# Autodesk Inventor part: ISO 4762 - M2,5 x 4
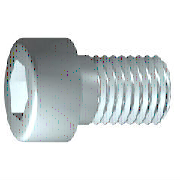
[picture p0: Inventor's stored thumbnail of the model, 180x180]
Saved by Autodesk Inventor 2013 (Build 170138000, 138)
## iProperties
Created: 2012-02
Part Number: ISO 4762 - M2,5 x 4
Material: Stainless Steel, 440C
Description: Hexagon Socket Head Cap Screw
Document SubType Name: Modeling
Standard: ISO 4762
Designer: rYan
Standard Revision: Fourth edition 2004-03-01
Standards Organization: ISO
Language: en-US
Size Designation: M2,5 x 4
Categories: <MemberInstance><Categories><Category DisplayName="Fasteners" InternalName="e4da775c-781d-43d5-af7c-5136215cf5a6" Mnemonic="FSTN"><Category DisplayName="Bolts"
Density: 7.75 g/cm^3
IsCustomPart: 0
Author: rYan
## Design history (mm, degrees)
sketch "Sketch1"
  geometry: L1 (-0.733, 0)-(4, 0); L2 (4, 0)-(4, 1.25); L3 (4, 1.25)-(1.125, 1.25); L4 (1.125, 1.25)-(0.849, 1.25); L5 (0.849, 1.25)-(0, 1.25); L6 (0, 1.25)-(0, 2.25); L7 (0, 2.25)-(-2.5, 2.25); L8 (-2.5, 2.25)-(-2.5, 1.155); L9 (-2.5, 1.155)-(-1.4, 1.155); L10 (-1.4, 1.155)-(-0.733, 0); L11 (-3.8, 0)-(5.3, 0) reference; L12 (0, -0.45)-(0, 2.7) reference; L13 (1.125, 1.25)-(0, 1.25)
  constraints: 22 end point, 6 parallel, 2 collinear, 2 perpendicular, 1 horizontal, 1 point on line
  dimensions: "d1" = 2.875 distance from line of L3.end L2 (= GEL); "d2" = 0.27615 distance of L4.end L3.end (computed from GAL); "d3" = 2.5 distance between parallel lines of L8 L6 (= KOH); "d4" = 1.1 distance of L8.end L9.end (= INTI); "d5" = 60 deg angle of L10 L1; "d6" = 2.5 diameter of L3 L1 (= GD); "d7" = 2.5 diameter of L5 L1 (= BDM); "d8" = 2.3094 diameter of L9 L1 (= 1.1547 x SW); "d9" = 4.5 diameter of L7 L1 (= KOD); "d26" = 4 distance between parallel lines of L12 L2 (= NLG)
revolve "Body" sketch "Sketch1" stored, may be unused: angle "d10" = 90 deg
sketch "Sketch2"
  geometry: L1 (0, -3.15)-(0, 3.15) reference; L2 (-3.15, 0)-(3.15, 0) reference; L3 (1.155, 0)-(0.577, -1); L4 (0.577, -1)-(-0.577, -1); L5 (-0.577, -1)-(-1.155, 0); L6 (-1.155, 0)-(-0.577, 1); L7 (-0.577, 1)-(0.577, 1); L8 (0.577, 1)-(1.155, 0); 2 further points
  constraints: 12 end point, 1 coincident, 1 horizontal alignment, 1 point on line, 12 other
extrude "Slot" join sketch "Sketch2" stored distance "d11" = 10; taper "d12" = 0 deg
workplane "Work Plane1"
fillet "Fillet2" dims "d30" = 0.1 (= R)
body "Solid1"
fillet "Fillet1" dims "d17" = 0.25 (= RR)
feature "Thread" dims "d13" = 2.875 (= GEL), "d14" = 0
chamfer "Chamfer1" distance "d15" = 0.27605 (= -0.5 x SPD + 0.5 x GD); stored, may be unused: second distance "d16" = 0.27605 (= GUL), angle "d27" = 45 deg
other parameters: "GD" = 2.5 [user parameter; used in 2 equation terms], "NLG" = 4 [user parameter; used in 1 equation term], "GEL" = 2.875 [user parameter; used in 2 equation terms], "KOD" = 4.5 [user parameter; used in 1 equation term], "KOH" = 2.5 [user parameter; used in 1 equation term], "INTI" = 1.1 [user parameter; used in 1 equation term], "GAL" = 0.27605 (= 0.61345 x PTC) [user parameter; used in 1 equation term], "GUL" = 0.27605 (= 0.61345 x PTC) [user parameter; used in 1 equation term], "BDM" = 2.5 (= NND) [user parameter; used in 1 equation term], "SW" = 2 [user parameter; used in 2 equation terms], "RR" = 0.25 [user parameter; used in 1 equation term], "SPD" = 1.94789 (= NND - 1.2269 x PTC) [user parameter; used in 1 equation term], "d19" = 0, "d28" = 0, "d29" = 0, "R" = 0.1 [user parameter; used in 1 equation term], "TOA" = 30 deg [user parameter], "GD1" = 1.94789 (= THREADDIA - 1.2269 x PTC) [user parameter], "THREADDIA" = 2.5 [user parameter; used in 1 equation term], "FAWI" = 45 deg [user parameter], "TPU" = 22.22222 (computed from PTC) [user parameter], "PTC" = 0.45 [user parameter; used in 5 equation terms], "NND" = 2.5 [user parameter; used in 2 equation terms], "E0" = 2.31 (= 1.155 x SW) [user parameter]
